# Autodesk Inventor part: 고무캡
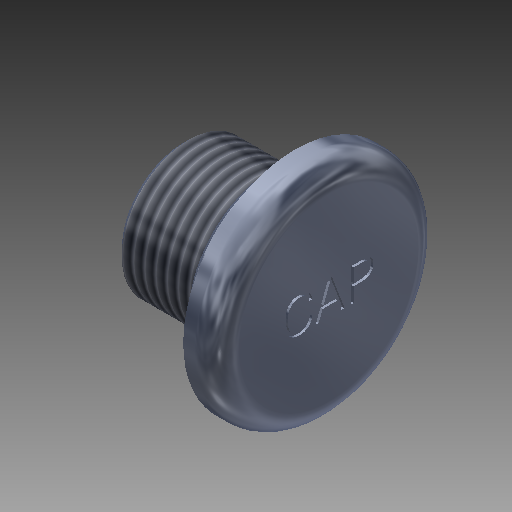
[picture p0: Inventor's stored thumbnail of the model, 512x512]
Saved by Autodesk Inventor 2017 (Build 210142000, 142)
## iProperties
Created: 2017-06
Part Number: 고무캡
Material: 고무
Document SubType Name: Modeling
Designer: mduedu
Density: 1 g/cm^3
Appearance: 고무 - 파란색 - 버전 1.1
Author: mduedu
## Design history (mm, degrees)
sketch "스케치1"
  geometry: L1 (0, 0)-(13, 0); L2 (13, 0)-(13, 10); L3 (13, 10)-(10, 10); L4 (0, 6)-(0, 0); L5 (0, 6)-(8, 6); L6 (8, 6)-(8, 8); L7 (8, 8)-(10, 8); L8 (10, 8)-(10, 10)
  constraints: 16 end point, 2 horizontal, 2 parallel, 2 perpendicular, 2 point on line, 1 vertical
  dimensions: "d0" = 20 diameter of L3 L1; "d2" = 12 diameter of L5 L1; "d6" = 5 distance between parallel lines of L2 L6; "d8" = 16 diameter of L7 L1; "d9" = 8 distance between parallel lines of L6 L4; "d32" = 2 distance of L6.end L7.end
revolve "회전1" sketch "스케치1" stored, may be unused: angle "d10" = 90 deg
hole "구멍1" diameter "d22" = 5; stored, may be unused: countersink angle "d26" = 90 deg, drill point angle "d28" = 0 deg; dims "d23" = 6, "d24" = 4, "d25" = 2, "d27" = 6, "d30" = 10, "d31" = 10
chamfer "모따기1" distance "d13" = 0.5; stored, may be unused: second distance "d14" = 2, angle "d15" = 45 deg
fillet "모깎기3" dims "d29" = 1
fillet "모깎기2" dims "d17" = 2
sketch "스케치3"
  geometry: 2 further points
  constraints: 1 coincident, 1 other
feature "엠보싱1" sketch "스케치3" dims "d18" = 0.2, "d19" = 0, "d29" = 1
feature "스레드1" dims "d33" = 10, "d34" = 0
node "솔리드1"
